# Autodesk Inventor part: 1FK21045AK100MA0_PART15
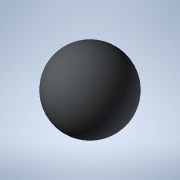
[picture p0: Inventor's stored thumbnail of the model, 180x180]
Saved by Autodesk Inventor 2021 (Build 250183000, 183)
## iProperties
Created: 2025-04
Part Number: 1FK21045AK100MA0_PART15
Material: Generic
Catalog Web Link: www.3dfindit.com
Description: -Servo synchronous motor
Document SubType Name: Modeling
Designer: psAdmin
Mass: 0.137258 g
Surface Area: 1.2868 cm^2
Volume: 0.137258 cm^3
Density: 1 g/cm^3
Appearance: PSOLRGB-212-217-219
Category: PARTsolutions
Title: 1FK21045AK100MA0_PART15
Author: Cadenas PARTsolutions
Comments: Servo synchronous motor
Sending System: PARTsolutions
Preprocessor: ST-DEVELOPER v19.3
PSOL_IDENT_0: {$CADENAS_DATA/23d-libs/siemens_ag/_cat_/e0/5f/1fk21045ak100ma0.prj},216 {VTYP=3D},{NB=1FK21045AK100
PSOL_IDENT_1: MA0_PART15},{LINA=1FK21045AK100MA0_PART15},{NN=1FK21045AK100MA0_PART15},{NOPRJ=TRUE},{DATE=19.08.202
PSOL_IDENT_2: 5 14:01:03},{GEOMDATE=30.07.2025 02:01:57},{VERSION=},{LINEID=10},{WBVAR=},{WBNUMERIC=}  {NB=1FK2104
PSOL_IDENT_3: 5AK100MA0_PART15},{LINA=1FK21045AK100MA0_PART15},{KT=DUMMY},{PREVIEW=../../../_pool_/0f/2c/p_d211_xx
PSOL_IDENT_4: _00438j.png},{DESCSHORT=SIMOTICS S-1FK2 HD, SINAMICS S210 3AC 400V-480V, 1.7 Nm, 6000 rpm},{DESCLONG=
PSOL_IDENT_5: SIMOTICS S-1FK2 HD servo motor M0=2.4 Nm; PN = 1.07 kW at nN=6000 rpm (380-480 V); PN = 0.75 kW at n
PSOL_IDENT_6: N=3000 rpm (200-240 V); with holding brake; degree of protection IP64; cylindrical shaft D19x40mm; a
PSOL_IDENT_7: bsolute encoder 22-bit + 12-bit multiturn (encoder AM22DQC); with OCC interface; plug size M17, rota
PSOL_IDENT_8: table; SIMOTICS S-1FK2 servomotorfor a wide range of uses in industrial environments. SIMOTICS S‑1FK
PSOL_IDENT_9: 2 servomotors are compact synchronous motors with a high dynamic performance that set themselves apa
PSOL_IDENT_10: rt as a result of their high power density, degree of protection and overload capability. The motors
PSOL_IDENT_11: are available in two variants: as High Dynamic variant (highest dynamic performance as a result of
PSOL_IDENT_12: the low intrinsic moment of inertia for applications demanding a high dynamic performance with low m
PSOL_IDENT_13: oved masses) - and as Compact variant (precise and stable closed-loop control for medium up to large
PSOL_IDENT_14: moved masses as a result of a medium intrinsic moment of inertia). SIMOTICSS‑1FK2 servomotors fully
PSOL_IDENT_15: exploit their strengths in a system with the SINAMICSS210 frequency converter and simple connection
PSOL_IDENT_16: using the one cable connection (OCC). Advantages include the short control and positioning times, f
PSOL_IDENT_17: ast and precise correction of disturbing quantities as well as stable control with a high dynamic pe
PSOL_IDENT_18: rformance. The servo motors can be configured to address a wide range of requirements. For example w
PSOL_IDENT_19: ith and without holding brake, IP64 or IP65 degree of protection, singleturn or multiturn absolute e
PSOL_IDENT_20: ncoders - to name just a few. Further, the servomotors are available in different shaft heights exte
PSOL_IDENT_21: nding from 20 to 100. A shaft sealing ring is available to achieve an IP65 degree of protection and
PSOL_IDENT_22: for subsequent mounting at the motor or as spare part. SIMOTICS - the optimum motor for each and eve
PSOL_IDENT_23: ry motion control application.},{INTNO=804766807114},{SUPPLIERALTNO=1FK2104-5AK10-0MA0},{MANUID=1FK2
PSOL_IDENT_24: 1045AK100MA0},{MANUNAME=Siemens},{MANUTYPEDESC=Synchronous motor 1FK2-HD 2,39 Nm},{AAU732=SIMOTICS},
PSOL_IDENT_25: {AAO057=S-1FK2},{AAU734=SIMOTICS S-1FK2 HD servo motor M0=2.4 Nm; PN = 1.07 kW at nN=6000 rpm (380-4
PSOL_IDENT_26: 80 V); PN = 0.75 kW at nN=3000 rpm (200-240 V); with holding brake; degree of protection IP64; cylin
PSOL_IDENT_27: drical shaft D19x40mm; absolute encoder 22-bit + 12-bit multiturn (encoder AM22DQC); with OCC interf
PSOL_IDENT_28: ace; plug size M17, rotatable;},{AAW338=Synchronous motor 1FK2-HD 2,39 Nm},{AAO742=SIMOTICS},{AAO663=
PSOL_IDENT_29: 4042948691236},{NOCUPEROU=1},{PRICEQUANTITY=1},{QUANTITYMIN=1},{QUANTITYINT=1},{CTN=85015100},{COO=D
PSOL_IDENT_30: E},{AAO676=1FK2104-5AK10-0MA0},{AAO677=Siemens AG},{ORDERUNIT=C62},{CONTENTUNIT=C62}
NB: 1FK21045AK100MA0_PART15
NT: Servo synchronous motor
NBSYN: $MANUID._PART15
LINA: 1FK21045AK100MA0_PART15
CATALOG: SIEMENS
PREVIEW: ../../../_pool_/0f/2c/p_d211_xx_00438j.png
DESCSHORT: SIMOTICS S-1FK2 HD, SINAMICS S210 3AC 400V-480V, 1.7 Nm, 6000 rpm
DESCLONG: SIMOTICS S-1FK2 HD servo motor M0=2.4 Nm; PN = 1.07 kW at nN=6000 rpm (380-480 V); PN = 0.75 kW at nN=3000 rpm (200-240 V); with holding brake; degree of protec
INTNO: 804766807114
SUPPLIERALTNO: 1FK2104-5AK10-0MA0
MANUID: 1FK21045AK100MA0
MANUNAME: Siemens
MANUTYPEDESC: Synchronous motor 1FK2-HD 2,39 Nm
AAU732: SIMOTICS
AAO057: S-1FK2
AAU734: SIMOTICS S-1FK2 HD servo motor M0=2.4 Nm; PN = 1.07 kW at nN=6000 rpm (380-480 V); PN = 0.75 kW at nN=3000 rpm (200-240 V); with holding brake; degree of protec
AAW338: Synchronous motor 1FK2-HD 2,39 Nm
AAO742: SIMOTICS
AAO663: 4042948691236.0
NOCUPEROU: 1
PRICEQUANTITY: 1
QUANTITYMIN: 1
QUANTITYINT: 1
CTN: 85015100
COO: DE
ARTICLENO: 1FK21045AK100MA0_PART15
BOMINFO: 1FK21045AK100MA0_PART15
CREATOR: CADENAS GmbH
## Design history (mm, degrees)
feature "2025_04_17_15_45_15_0090"
body "Solid1"
